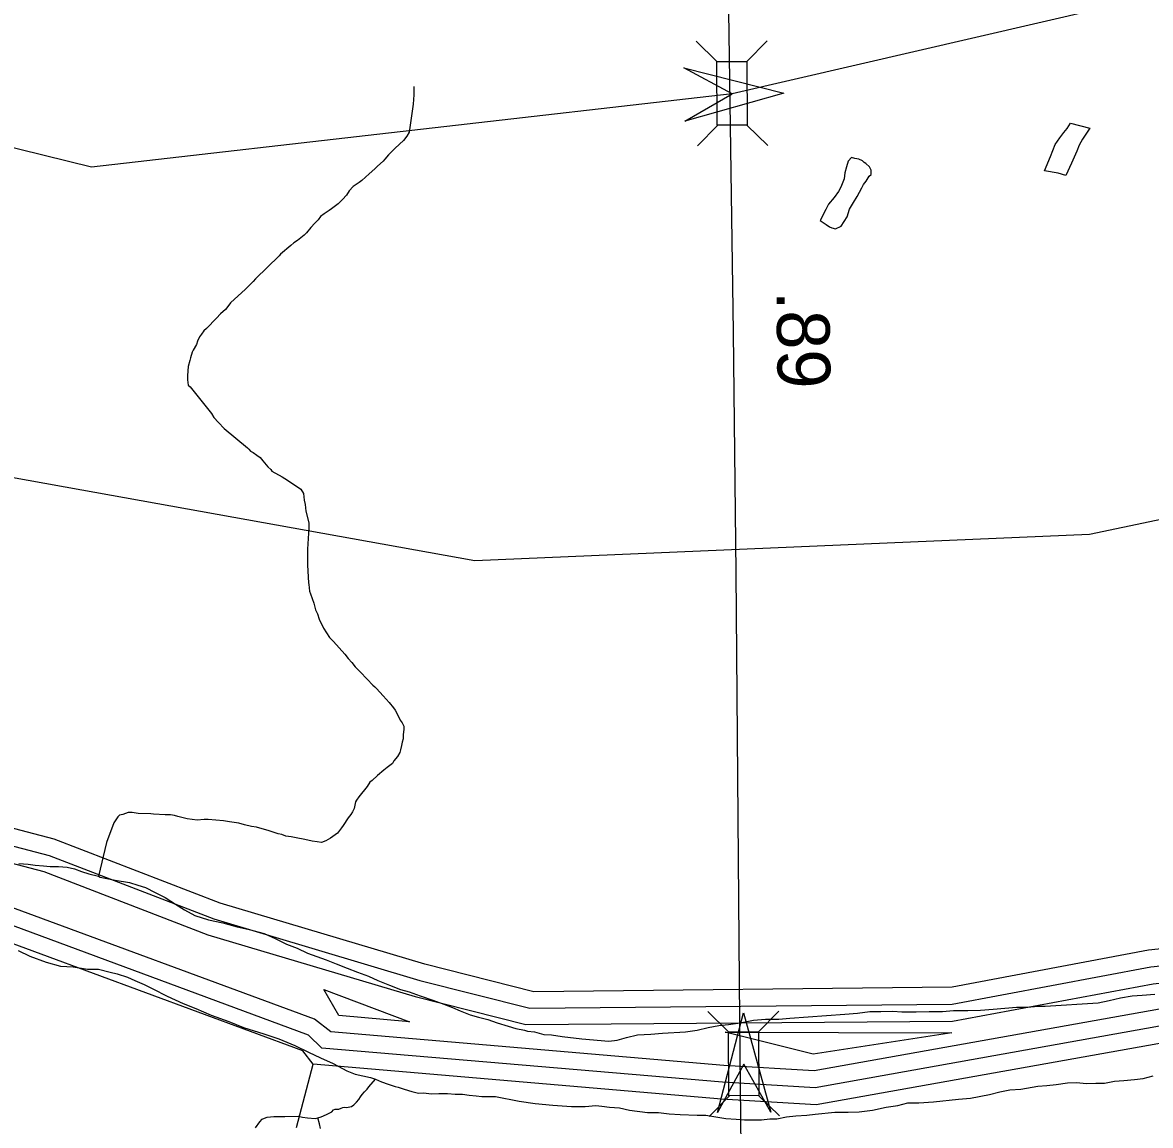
# Model space of a CAD drawing. Extents: x 2206922 to 2357709, y 510027 to 673830.
# Drawn here: x 2323470 to 2326143, y 551723 to 554336 of the extents above; entities that cross this region are included whole.
import ezdxf

# ---------------------------------------------------------------- set-up
doc = ezdxf.new("R2010")
doc.units = 0
for name, color, linetype in [('Exist Hydrographic Buffer Line', 7, 'Continuous'), ('Exist Hydrographic Creek Single Shore', 7, 'Continuous'), ('Exist Hydrographic Misc Water Feature', 7, 'Continuous'), ('Exist Hydrographic River Shore', 7, 'Continuous'), ('Exist Road Primary NC Attributed', 7, 'Continuous'), ('Exist Road Primary NC Service Mileage Hundredths English Label', 7, 'Continuous'), ('Exist Road Primary NC Structure Standard Bridge CELL', 7, 'Continuous'), ('Exist Road Secondary Structure Standard Bridge Attributed CELL', 7, 'Continuous')]:
    doc.layers.add(name, color=color, linetype=linetype)

msp = doc.modelspace()

# ---------------------------------------------------------------- linework, layer by layer
at = {"layer": 'Exist Hydrographic Buffer Line'}
for points in [[(2321186.1, 552806.9), (2322426.5, 552635.2), (2322884.1, 552532.8), (2323532.3, 552362.9), (2323923.1, 552212.3), (2324411.2, 552066.7), (2324671.8, 552001.2), (2325673, 552010.5), (2326143.4, 552098.5), (2326499.8, 552135.7), (2326964.7, 552293.9), (2327492.7, 552576.8), (2328139.6, 552974.8), (2328433.5, 553223.1), (2328603.7, 553431.9)], [(2321172.6, 552769.4), (2322419.3, 552595.8), (2322874.5, 552493.9), (2323520, 552324.8), (2323908.8, 552175), (2324399.9, 552028.3), (2324662.1, 551962.4), (2325673.3, 551970.5), (2326149.2, 552058.9), (2326503.5, 552096.9), (2326230.2, 552010.6), (2325345.8, 551852.1)], [(2325345.8, 551852.1), (2325131.3, 551865.3), (2324200.2, 551944.7), (2324161.4, 551974.8), (2323416.2, 552250), (2322639.3, 552438.3), (2321253.8, 552697.6)], [(2326239.4, 551971.6), (2325348.2, 551811.9), (2325128.6, 551825.4), (2324179.2, 551906.3), (2324147.3, 551937.3), (2323402.3, 552212.4), (2322630.1, 552399.4), (2321244.7, 552658.6)], [(2324386.6, 551968.9), (2324219, 551983.2), (2324183.8, 552045.1), (2324386.6, 551968.9)], [(2325343.5, 551892.3), (2325134.6, 551944.4), (2325672, 551942.4), (2325343.5, 551892.3)]]:
    msp.add_lwpolyline(points, dxfattribs=at)
at = {"layer": 'Exist Hydrographic Creek Single Shore'}
for points in [[(2328413.8, 554978.6), (2327117.9, 554579.7), (2326022.6, 554368.1), (2325151.5, 554166.9), (2323633.3, 553993.1), (2322555.1, 554259), (2321778.3, 554604.6)], [(2328672.9, 553945), (2326769.4, 553284.8), (2325997.7, 553123), (2324541.5, 553060.7), (2323570.6, 553235), (2322811.4, 553372), (2321728.6, 553446.7)], [(2324118.5, 551718.6), (2324158.5, 551867.9)]]:
    msp.add_lwpolyline(points, dxfattribs=at)
at = {"layer": 'Exist Hydrographic Misc Water Feature'}
for points in [[(2324396.8, 554184.7), (2324396.8, 554164.8), (2324395, 554142.8), (2324385.5, 554076.5), (2324380, 554066.4), (2324372, 554056.2), (2324352.3, 554038.1), (2324336.5, 554022.2), (2324328.5, 554012.1), (2324324.4, 554007.8), (2324310.9, 553995.7), (2324304.7, 553989.7), (2324290.8, 553977.6), (2324273.4, 553961.6), (2324267, 553957.2), (2324253.1, 553947.2), (2324243.8, 553937.2), (2324237.5, 553926.8), (2324227.6, 553916.9), (2324217.8, 553906.7), (2324201.8, 553894.9), (2324196.1, 553890.5), (2324184.2, 553882.5), (2324176, 553876.5), (2324170.2, 553868.4), (2324162.2, 553860.3), (2324152.4, 553850.4), (2324142.7, 553838.1), (2324136.6, 553832.1), (2324121, 553819.8), (2324112.8, 553813.8), (2324105, 553807.7), (2324081.2, 553787.3), (2324077.5, 553783.4), (2324021.8, 553729), (2324016, 553722.5), (2324011.9, 553718.7), (2323998.2, 553704.6), (2323962.5, 553672.2), (2323958.6, 553666.3), (2323950.4, 553656.2), (2323938.7, 553646.2), (2323928.9, 553635.9), (2323905.3, 553611.5), (2323899.1, 553605.5), (2323893.6, 553597.4), (2323889.1, 553591.6), (2323883.8, 553581.5), (2323881.5, 553573.3), (2323873.7, 553559.4), (2323871.7, 553555.3), (2323867.6, 553541.3), (2323866.1, 553535.4), (2323862.2, 553521), (2323860.2, 553499.4), (2323860.6, 553489.2), (2323862.4, 553477.2), (2323866.5, 553473.3), (2323917.6, 553409.7), (2323923.1, 553399.9), (2323933.6, 553388.2), (2323947.3, 553374.4), (2324002.3, 553328.8), (2324006, 553325), (2324009.9, 553320.8), (2324016, 553317), (2324024.4, 553310.9), (2324032.4, 553305.2), (2324038.8, 553297.4), (2324050.5, 553283.4), (2324058.3, 553277.4), (2324060.7, 553273.4), (2324084.7, 553259.6), (2324090.9, 553255.8), (2324121.2, 553235.9), (2324129.2, 553230.3), (2324135.6, 553220.4), (2324137.2, 553204.3), (2324139.3, 553194.2), (2324141.3, 553178.5), (2324147.7, 553150.4), (2324148.3, 553138.6), (2324144.6, 553088.4), (2324145.2, 553058.3), (2324145.2, 553050.6), (2324147.5, 553008.5), (2324147.7, 553004.5), (2324149.7, 552988.7), (2324151.8, 552982.7), (2324160, 552960.8), (2324164.1, 552944.8), (2324168.4, 552934.8), (2324172.3, 552922.8), (2324182.7, 552901), (2324196.9, 552879), (2324206.7, 552869.4), (2324233.2, 552839.5), (2324241.4, 552829.7), (2324249.6, 552819.6), (2324257.6, 552809.9)], [(2325942.3, 553973.2), (2325924, 553979.2), (2325891.8, 553984.9), (2325905.6, 554018.9), (2325917.1, 554047.1), (2325927.5, 554063), (2325937.2, 554075.4), (2325945.2, 554085.1), (2325952.7, 554097.4), (2325998.9, 554085.9), (2325981.2, 554059.8), (2325973.4, 554045.6), (2325967.7, 554031.5), (2325961.6, 554017.4), (2325955.8, 554003.2), (2325942.3, 553973.2)], [(2325359.7, 553867.1), (2325373.9, 553857.2), (2325381.9, 553851.6), (2325387.8, 553849.4), (2325396, 553847.4), (2325409.8, 553853.4), (2325423.7, 553875.7), (2325429.2, 553893.9), (2325439.1, 553909.9), (2325447.1, 553924.1), (2325452.8, 553934.1), (2325458.8, 553944.2), (2325462.7, 553952.1), (2325468.8, 553960.1), (2325476.2, 553972.4), (2325480.3, 553976.2), (2325480.3, 553986.3), (2325476.6, 553994.2), (2325468, 554002), (2325464.1, 554004.2), (2325460.2, 554008.1), (2325451.8, 554012.1), (2325442, 554014), (2325434.2, 554016), (2325426.2, 554007.9), (2325422.5, 553993.8), (2325418.4, 553979.9), (2325416.5, 553965.5), (2325408.9, 553945.6), (2325403, 553935.5), (2325392.9, 553921.6), (2325379.2, 553905.4), (2325373.5, 553893.4), (2325359.7, 553867.1)], [(2324257.6, 552809.9), (2324269.3, 552798), (2324285.9, 552780.1), (2324300, 552766.2), (2324304.1, 552762.3), (2324308.2, 552758.4), (2324324.4, 552740.6), (2324338.4, 552724.8), (2324348.6, 552712.7), (2324352.7, 552706.8), (2324358.9, 552694.9), (2324364.8, 552683), (2324368.9, 552677.1), (2324373.2, 552669.2), (2324373.2, 552661.1), (2324371.2, 552649.2), (2324371.2, 552639.1), (2324369.5, 552631.3), (2324367.7, 552623), (2324365.6, 552613.2), (2324363.8, 552607), (2324357.8, 552596.9), (2324349.8, 552587.2), (2324346.2, 552580.8), (2324333.9, 552570.9), (2324326.1, 552564.8), (2324310.5, 552552.5), (2324298.2, 552540.6), (2324292.4, 552536.2), (2324286.5, 552526.1), (2324266.8, 552501.9), (2324260.6, 552493.9), (2324258.8, 552490.1), (2324255.3, 552474), (2324251.4, 552465.7), (2324247.3, 552459.8), (2324241.4, 552451.8), (2324229.5, 552433.7), (2324225.6, 552427.8), (2324215.7, 552415.5), (2324199.7, 552403.3), (2324188.1, 552397.4), (2324178, 552393.2), (2324167.8, 552395.1), (2324156.3, 552396.9), (2324138.2, 552400.8), (2324117.9, 552404.7), (2324106, 552406.5), (2324093.9, 552408.3), (2324083.9, 552412.3), (2324075.7, 552414.3), (2324063.6, 552418.1), (2324051.9, 552421.9), (2324037.8, 552425.7), (2324023.8, 552429.4), (2324011.9, 552431.2), (2323995.5, 552435.3), (2323981.8, 552439), (2323971.3, 552440.9), (2323959.8, 552442.7), (2323945.7, 552444.8), (2323927.6, 552446.3), (2323909.8, 552448.2), (2323899.6, 552448.1), (2323883.4, 552446), (2323859.4, 552449.7), (2323837.8, 552455.4), (2323829.6, 552457.4), (2323819.8, 552459.3), (2323807.5, 552459.1), (2323779.6, 552460.9), (2323773.6, 552461), (2323743.3, 552462.3), (2323729.6, 552464.3), (2323719.5, 552464.2), (2323707.6, 552459.9), (2323699.6, 552457.9), (2323695.5, 552454), (2323686.1, 552439.7), (2323668.3, 552393.7), (2323649.2, 552313.4)], [(2323460.9, 552343.4), (2323483.1, 552341.7), (2323499.1, 552340.1), (2323519.2, 552338.3), (2323535, 552336.3), (2323554.9, 552336.5), (2323575, 552334.7)], [(2323575, 552334.7), (2323593, 552330.8), (2323609.2, 552325.1), (2323626.8, 552319.2), (2323649.2, 552313.4)], [(2323649.2, 552313.4), (2323653.3, 552311.6), (2323673.4, 552307.7), (2323689.4, 552304.1), (2323723.2, 552298.3), (2323743.1, 552292.4), (2323761.3, 552286.8), (2323783.5, 552275), (2323807.5, 552263.2), (2323831.7, 552247.5), (2323853.6, 552233.6), (2323878.2, 552220.2), (2323910, 552210.5), (2323944, 552203), (2323978.3, 552193.4), (2324006.6, 552187.5), (2324042.3, 552177.6), (2324068.5, 552166), (2324094.8, 552152.3), (2324120.6, 552142.7), (2324144.6, 552131), (2324167.1, 552123.1), (2324189.3, 552115.4), (2324213.1, 552105.7), (2324239.1, 552096.1), (2324263.5, 552086.4), (2324289.4, 552076.4), (2324311.7, 552066.5), (2324339.4, 552055.1), (2324365.4, 552045.5), (2324385.7, 552039.6), (2324411.8, 552030), (2324442.1, 552020.2), (2324468, 552010.6), (2324488.1, 552002.7), (2324506.3, 551994.7), (2324530.1, 551985.4), (2324550.4, 551979.5), (2324572.5, 551973.8), (2324594.1, 551966.1), (2324620.3, 551958), (2324638.6, 551952.5), (2324658.9, 551948.6), (2324666.4, 551946.6), (2324682.9, 551945), (2324704.8, 551938.8), (2324722.8, 551937.4), (2324748.5, 551933.5), (2324794.8, 551928.1), (2324858.8, 551922.5), (2324878.9, 551924.9), (2324900.6, 551931.3), (2324926.9, 551937.5), (2324958.6, 551939.6), (2324986.5, 551941.9), (2325040.3, 551944.7), (2325068.1, 551949), (2325094.2, 551955.3), (2325120, 551959.5), (2325142.2, 551961.9), (2325170.1, 551966.2), (2325202, 551972.3), (2325230.1, 551974.6), (2325262.1, 551975), (2325288, 551977.2), (2325418, 551986.9), (2325447.9, 551988.8), (2325477.6, 551993.3), (2325503.5, 551993.4), (2325531.8, 551994.1), (2325553.5, 551992), (2325587.5, 551992.6), (2325617.9, 551992.9), (2325649.7, 551992.9), (2325675.7, 551995.5), (2325709.5, 551995.7), (2325739.9, 551996), (2325769.6, 551998.4), (2325797.1, 552000.8), (2325825.2, 552003), (2325849.4, 552003.4), (2325877.5, 552005.7), (2325893.3, 552005.8), (2326019, 552013.2), (2326045, 552019.4), (2326071.3, 552025.6), (2326099.1, 552029.9), (2326122.9, 552032), (2326153.1, 552034.4)], [(2323458.9, 552137.7), (2323487.2, 552124.1), (2323525.3, 552110.3), (2323559.4, 552100.6), (2323589.3, 552099), (2323623.8, 552093.4), (2323649.6, 552093.6), (2323677.3, 552086.2), (2323693.7, 552082.1), (2323717.9, 552074.4), (2323735.7, 552066.4), (2323757.9, 552057), (2323778, 552047.1), (2323812, 552029.4), (2323850.3, 552011.9), (2323880.3, 552000.1), (2323916.8, 551984.5), (2323958.8, 551969.2), (2323993.1, 551955.5), (2324041, 551939.8), (2324076.9, 551928.3), (2324115.1, 551912.8), (2324147.5, 551897), (2324175.8, 551883.4), (2324205.3, 551869.6), (2324238.1, 551852.2), (2324257.6, 551844.4), (2324294.3, 551836.8), (2324306, 551833)], [(2324169, 551741.3), (2324177, 551743.3), (2324182.9, 551745.7), (2324191.3, 551749.7), (2324195, 551751.6), (2324202.8, 551755.7), (2324206.5, 551760), (2324210.8, 551761.8), (2324218.8, 551761.8), (2324224.8, 551764.1), (2324228.9, 551765.9), (2324232.8, 551766.2), (2324236.9, 551765.9), (2324248.8, 551768.2), (2324254.5, 551772.2), (2324260.6, 551778.2), (2324266.8, 551784.5), (2324270.3, 551790.5), (2324274.4, 551796.4), (2324280.3, 551802.4), (2324286.1, 551808.8), (2324290.2, 551814.7), (2324306, 551833)], [(2324306, 551833), (2324320.1, 551826.8), (2324336.3, 551821.1), (2324352.3, 551815.5), (2324360.1, 551813.5), (2324374.2, 551809.4), (2324392.5, 551803.8), (2324408.3, 551799.8), (2324420.2, 551800), (2324438.2, 551798.1), (2324456.1, 551798.6), (2324476.6, 551798.8), (2324494.6, 551797), (2324512.5, 551797.1), (2324528.2, 551795.1), (2324544.2, 551793.5), (2324558.2, 551791.4), (2324570.3, 551791.6), (2324590.2, 551791.9), (2324646.6, 551780.5), (2324684.3, 551774.9), (2324726.1, 551771.4), (2324748.5, 551769.7), (2324770.2, 551768), (2324802.6, 551768), (2324828, 551770.7), (2324842.2, 551768.6), (2324860.6, 551766.6), (2324884.6, 551765), (2324908.2, 551759.4), (2324950.6, 551753.8), (2324976.7, 551754), (2325002.3, 551750.5), (2325028.4, 551748.7), (2325068.6, 551747.1), (2325088.6, 551747.3), (2325112.6, 551743.7), (2325136.6, 551739.6), (2325160.6, 551738.1), (2325180.7, 551736.3), (2325202.9, 551736.6), (2325220.7, 551736.7), (2325240.6, 551739), (2325256.8, 551739), (2325280.4, 551743.2), (2325302.5, 551745.5), (2325328.4, 551747.7), (2325348.2, 551750), (2325394.6, 551754.4), (2325426.4, 551754.9), (2325452.4, 551755.4), (2325484.2, 551759.5), (2325516.4, 551766.1), (2325544.1, 551770), (2325567.9, 551776.5), (2325593.7, 551776.7), (2325628.1, 551778.9), (2325687.8, 551785.7), (2325715.9, 551787.9), (2325761.4, 551796.5), (2325785.4, 551802.6), (2325809.6, 551807.1), (2325835.4, 551809.3), (2325875.6, 551815.8), (2325897.2, 551817.8), (2325919.3, 551820.2), (2325945.6, 551824.4), (2325967.3, 551824.7), (2325991.1, 551822.7), (2326012.8, 551823.1), (2326033.3, 551823.3), (2326057.1, 551827.9), (2326079.1, 551829.8), (2326104.9, 551832), (2326125.2, 551834.2), (2326148.8, 551840.4)], [(2324021.6, 551717.7), (2324031.6, 551732), (2324037.1, 551738), (2324043.1, 551740), (2324049, 551742.4), (2324065, 551744.4), (2324075.3, 551744.5), (2324085.1, 551744.6), (2324091.1, 551744.5), (2324122.9, 551745), (2324133.3, 551743), (2324144.8, 551741.3), (2324163.2, 551739.3), (2324169, 551741.3)], [(2324175.3, 551715.6), (2324173.1, 551727.3), (2324169, 551741.3)]]:
    msp.add_lwpolyline(points, dxfattribs=at)
at = {"layer": 'Exist Hydrographic River Shore'}
for points in [[(2324158.5, 551867.9), (2324133.5, 551899.8), (2323388.6, 552174.9), (2322620.4, 552360.5), (2321235.5, 552619.6), (2320449.6, 552843.9), (2319965.4, 552922.8), (2319499.5, 552933.6), (2318417.5, 552896.4), (2318116.5, 552936.8), (2318049.4, 552983.3), (2317965.3, 553091.5), (2317930.5, 553191.8), (2317821.4, 553282.7), (2317260.4, 553558.6), (2316714.3, 553953.3), (2316589.4, 554043.4), (2316472.4, 554051.9)], [(2328672.9, 553945), (2328653.7, 553631), (2328572.7, 553457.1), (2328407.6, 553253.6), (2328118.7, 553008.9), (2327473.6, 552612.1), (2326951.5, 552331.8), (2326495.5, 552175.5), (2326137.7, 552138.2), (2325672.6, 552050.4), (2324681.6, 552040), (2324422.6, 552105), (2323937.5, 552249.6), (2323544.6, 552401.1), (2322893.6, 552571.6), (2322433.4, 552674.6), (2321199.4, 552844.7)], [(2326248.6, 551932.6), (2325350.5, 551771.6), (2325125.6, 551785.5), (2324158.5, 551867.9)]]:
    msp.add_lwpolyline(points, dxfattribs=at)
at = {"layer": 'Exist Road Primary NC Attributed'}
for points in [[(2325160.4, 553033.1), (2325154.2, 553602.1), (2325130.5, 555231.3), (2325127.1, 555522.2), (2325121.4, 556002)], [(2325170.4, 551891.2), (2325168.9, 552064.2), (2325160.4, 553033.1)], [(2325186.2, 551331.2), (2325180.7, 551440.8), (2325172.5, 551667.9), (2325170.4, 551891.2)]]:
    msp.add_lwpolyline(points, dxfattribs=at)
at = {"layer": 'Exist Road Primary NC Structure Standard Bridge CELL'}
for p, q in [((2325066.3, 554292.2), (2325115.3, 554243.6)), ((2325234.4, 554293), (2325185.9, 554244)), ((2325117.3, 554092.5), (2325068.8, 554043.5)), ((2325186.3, 554092.9), (2325235.4, 554044.3)), ((2325093.7, 551993.1), (2325142.8, 551944.6)), ((2325261.9, 551994.1), (2325213.4, 551945.1)), ((2325145, 551793.5), (2325096.5, 551744.5)), ((2325214, 551794), (2325263.1, 551745.5))]:
    msp.add_line(p, q, dxfattribs=at)
for points in [[(2325185.9, 554244), (2325186.7, 554092.9), (2325116.1, 554092.5), (2325115.3, 554243.6)], [(2325213.4, 551945.1), (2325214.3, 551794), (2325143.7, 551793.5), (2325142.8, 551944.6)]]:
    msp.add_lwpolyline(points, close=True, dxfattribs=at)
at = {"layer": 'Exist Road Secondary Structure Standard Bridge Attributed CELL'}
for points in [[(2325037, 554228.3), (2325273.4, 554168.6), (2325038.8, 554102.1), (2325151.5, 554166.9)], [(2325116.4, 551754), (2325178.5, 551989.8), (2325242.7, 551754.6), (2325179.1, 551867.9)]]:
    msp.add_lwpolyline(points, close=True, dxfattribs=at)

# ---------------------------------------------------------------- texts
at = {"layer": 'Exist Road Primary NC Service Mileage Hundredths English Label'}
msp.add_text('.89', height=125, rotation=270.8152, dxfattribs=at).set_placement((2325256.1, 553700.3))

doc.saveas('drawing.dxf')
